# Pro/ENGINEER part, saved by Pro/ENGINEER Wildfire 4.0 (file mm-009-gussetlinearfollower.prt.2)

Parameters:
  METRIC = "NO"

Other parameters: PITCH, DRILL_POINT_ANGLE, DRILL_DEPTH, DRILL_DIAMETER, THREAD_DIAMETER, THREADS_PER_INCH, THREAD_DEPTH, THREAD_LENGTH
